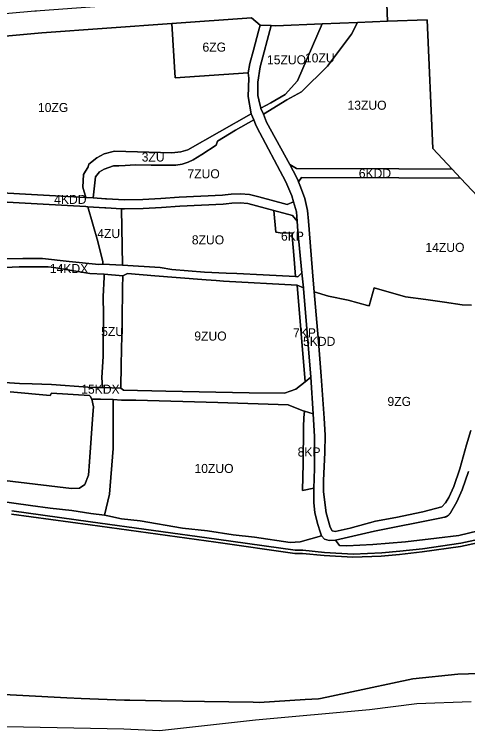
# Model space of a CAD drawing. Extents: x 7417411 to 7420955, y 5545251 to 5546537.
# Drawn here: x 7420138 to 7420638, y 5545251 to 5546041 of the extents above; entities that cross this region are included whole.
import ezdxf

# ---------------------------------------------------------------- set-up
doc = ezdxf.new("R2010")
doc.units = 0
doc.layers.add('linie_rozgraniczajace', color=7, linetype='Continuous')
doc.layers.add('oznaczenia_przeznaczen', color=7, linetype='Continuous')

msp = doc.modelspace()

# ---------------------------------------------------------------- linework, layer by layer
at = {"layer": 'linie_rozgraniczajace'}
for points in [[(7420549.68, 5546033.24), (7420547.73, 5546081.2), (7420586.45, 5546082.77), (7420609, 5546083.69), (7420626.25, 5546084.39), (7420650.88, 5546084.15), (7420723.84, 5546106.56), (7420725.48, 5546091.44), (7420726.07, 5546087.79), (7420729, 5546075.63), (7420734.51, 5546063.64), (7420745.13, 5546048.91), (7420772.59, 5546019.84), (7420827.71, 5545793.69), (7420693.29, 5545793.41), (7420630.15, 5545860.23), (7420620.66, 5545870.27), (7420599.42, 5545892.75), (7420593.29, 5546035.01)], [(7420311.58, 5546030.68), (7420399.32, 5546036.96), (7420409, 5546029), (7420407.22, 5546022.29), (7420401.63, 5546001.22), (7420397.75, 5545986.58), (7420395.97, 5545976.33), (7420315.35, 5545971.04)], [(7420409.62, 5545937.58), (7420420.78, 5545943.38), (7420436.67, 5545952.35), (7420450.38, 5545967.4), (7420477.28, 5546030.3), (7420516.55, 5546031.9), (7420509.68, 5546018.99), (7420483.49, 5545983.7), (7420454.77, 5545955.32), (7420438.37, 5545946.45), (7420412.54, 5545930.62), (7420409.83, 5545937.09)], [(7420412.54, 5545930.62), (7420438.37, 5545946.45), (7420454.77, 5545955.32), (7420483.49, 5545983.7), (7420509.68, 5546018.99), (7420516.55, 5546031.9), (7420549.68, 5546033.24), (7420593.29, 5546035.01), (7420599.42, 5545892.75), (7420620.66, 5545870.27), (7420561.9, 5545870.54), (7420449.2, 5545870.81), (7420441.8, 5545875.21), (7420416.17, 5545922.01)], [(7420406.63, 5545951.44), (7420406.37, 5545966.02), (7420408.99, 5545983.08), (7420421.08, 5546028.46), (7420426.19, 5546028.23), (7420477.28, 5546030.3), (7420450.38, 5545967.4), (7420436.67, 5545952.35), (7420420.78, 5545943.38), (7420409.62, 5545937.58), (7420407.64, 5545946.76)], [(7420213.5, 5545850.07), (7420214.18, 5545864.21), (7420219.24, 5545872.82), (7420219.99, 5545875.81), (7420228.89, 5545882.73), (7420236.89, 5545887.08), (7420248.36, 5545889.85), (7420311.71, 5545888.04), (7420321.7, 5545889.12), (7420329.43, 5545891.48), (7420399.25, 5545931.11), (7420402.01, 5545924.55), (7420381.77, 5545913.12), (7420361.98, 5545900.88), (7420360.67, 5545896.5), (7420344.81, 5545886.32), (7420335.17, 5545880.56), (7420329.45, 5545877.87), (7420322.83, 5545875.7), (7420316.1, 5545874.61), (7420305.12, 5545874.36), (7420288.91, 5545874.59), (7420271.15, 5545874.73), (7420260.03, 5545874.3), (7420253.08, 5545873.95), (7420247.32, 5545873.9), (7420236.88, 5545870.16), (7420231.96, 5545867), (7420227.53, 5545861.6), (7420224.72, 5545838.38), (7420217.44, 5545838.82), (7420216.76, 5545838.86)], [(7420224.72, 5545838.38), (7420227.53, 5545861.6), (7420231.96, 5545867), (7420236.88, 5545870.16), (7420247.32, 5545873.9), (7420253.08, 5545873.95), (7420260.03, 5545874.3), (7420271.15, 5545874.73), (7420288.91, 5545874.59), (7420305.12, 5545874.36), (7420316.1, 5545874.61), (7420322.83, 5545875.7), (7420329.45, 5545877.87), (7420335.17, 5545880.56), (7420344.81, 5545886.32), (7420360.67, 5545896.5), (7420361.98, 5545900.88), (7420381.77, 5545913.12), (7420402.01, 5545924.55), (7420404.07, 5545919.66), (7420405.46, 5545916.36), (7420437.42, 5545856.26), (7420443.87, 5545840.74), (7420445.93, 5545834.02), (7420438.75, 5545830.95), (7420407.56, 5545839.5), (7420397.22, 5545842.04), (7420387.44, 5545842.88), (7420377.1, 5545842.58), (7420370.37, 5545841.76), (7420367.42, 5545841.36), (7420319.7, 5545839.23), (7420299.6, 5545837.83), (7420279.54, 5545836.78), (7420259.46, 5545836.2), (7420239.44, 5545837.49), (7420238.46, 5545837.55)], [(7420441.8, 5545875.21), (7420449.2, 5545870.81), (7420561.9, 5545870.54), (7420620.66, 5545870.27), (7420630.15, 5545860.23), (7420561.86, 5545860.54), (7420454.72, 5545860.8), (7420451.47, 5545856.11), (7420450.64, 5545858.37), (7420445.6, 5545868.28)], [(7420218.85, 5545828.72), (7420237.85, 5545827.57), (7420238.81, 5545827.51), (7420256.11, 5545826.4), (7420257.17, 5545764.03), (7420235.59, 5545765.33), (7420235.53, 5545767.93), (7420230.09, 5545790.18)], [(7420257.17, 5545764.03), (7420256.11, 5545826.4), (7420259.29, 5545826.19), (7420279.94, 5545826.79), (7420300.21, 5545827.85), (7420320.27, 5545829.24), (7420368.32, 5545831.4), (7420371.64, 5545831.85), (7420377.84, 5545832.6), (7420387.16, 5545832.87), (7420395.59, 5545832.15), (7420405.04, 5545829.82), (7420424.16, 5545824.58), (7420426.5, 5545800.48), (7420433.56, 5545799.64), (7420444.66, 5545799.96), (7420444.4, 5545796.2), (7420445.68, 5545779.62), (7420446.83, 5545766.11), (7420447.9, 5545751.54), (7420412.28, 5545753.44), (7420383.22, 5545754.99), (7420371.38, 5545755.22), (7420347.53, 5545756.55), (7420311.55, 5545759.45), (7420298.58, 5545761.69)], [(7420424.16, 5545824.58), (7420444.7, 5545818.95), (7420449.84, 5545812.63), (7420450.54, 5545801.74), (7420455.02, 5545755.91), (7420450.52, 5545751.33), (7420447.9, 5545751.54), (7420446.83, 5545766.11), (7420445.68, 5545779.62), (7420444.4, 5545796.2), (7420444.66, 5545799.96), (7420433.56, 5545799.64), (7420426.5, 5545800.48)], [(7420255.48, 5545628.56), (7420255.88, 5545654.51), (7420256.63, 5545703.06), (7420257.19, 5545739.02), (7420257.39, 5545752.37), (7420262.63, 5545755.02), (7420293.01, 5545752.57), (7420344.56, 5545748.43), (7420349.39, 5545748.04), (7420360.64, 5545747.14), (7420368.45, 5545746.7), (7420449.8, 5545742.11), (7420458.59, 5545635.39), (7420448.38, 5545627.55), (7420435.87, 5545622.9), (7420396.79, 5545623.49), (7420304.83, 5545625.3), (7420258.1, 5545626.42)], [(7420234.38, 5545640.35), (7420235.68, 5545663.55), (7420236.21, 5545709.56), (7420235.94, 5545729.77), (7420237.04, 5545750.93), (7420236.91, 5545754.1), (7420257.39, 5545752.37), (7420257.19, 5545739.02), (7420256.63, 5545703.06), (7420255.88, 5545654.51), (7420255.48, 5545628.56), (7420235.08, 5545629.07)], [(7420449.8, 5545742.11), (7420449.98, 5545742.1), (7420456.88, 5545739.33), (7420456.95, 5545738.44), (7420464.84, 5545640.48), (7420458.59, 5545635.39)], [(7420237.5, 5545488.39), (7420242.85, 5545511.38), (7420246.89, 5545561.88), (7420246.81, 5545587.87), (7420246.82, 5545615.97), (7420255.97, 5545615.4), (7420271.94, 5545615.08), (7420362.25, 5545612.52), (7420439.92, 5545610.15), (7420457.39, 5545603.27), (7420457.89, 5545603.13), (7420457.23, 5545596.29), (7420456.97, 5545585.54), (7420456.42, 5545545.55), (7420455.82, 5545515.52), (7420468.36, 5545518.32), (7420468.21, 5545501.91), (7420469.34, 5545491.35), (7420472.14, 5545479.1), (7420475.44, 5545468.83), (7420476.53, 5545465.42), (7420453.04, 5545459.11), (7420442.29, 5545458.22), (7420402.85, 5545464.11), (7420379.1, 5545466.57), (7420351.1, 5545470.94), (7420323.49, 5545473.92), (7420276.77, 5545482.08), (7420256.26, 5545484.48), (7420240.91, 5545487.68)], [(7420455.82, 5545515.52), (7420456.42, 5545545.55), (7420456.97, 5545585.54), (7420457.23, 5545596.29), (7420457.89, 5545603.13), (7420467.47, 5545600.36), (7420468.95, 5545575), (7420468.86, 5545540.26), (7420468.44, 5545528.34), (7420468.36, 5545518.32)]]:
    msp.add_lwpolyline(points, close=True, dxfattribs=at)
for points in [[(7419980.1, 5546028.55), (7420160.42, 5546044.76), (7420162.3, 5546044.92), (7420166.39, 5546045.27), (7420221.35, 5546049.28), (7420309.21, 5546055.57), (7420395.44, 5546066.68), (7420396.55, 5546067.81), (7420416.28, 5546087.9), (7420428.12, 5546089.95), (7420441.86, 5546076.9), (7420491.12, 5546078.9), (7420528.94, 5546080.44), (7420547.73, 5546081.2), (7420549.68, 5546033.24), (7420516.55, 5546031.9), (7420477.28, 5546030.3), (7420426.19, 5546028.23), (7420421.08, 5546028.46), (7420409, 5546029), (7420399.32, 5546036.96), (7420311.58, 5546030.68), (7420168.36, 5546020.35), (7419957.04, 5546001.38)], [(7419957.04, 5546001.38), (7420168.36, 5546020.35), (7420311.58, 5546030.68), (7420315.35, 5545971.04), (7420395.97, 5545976.33), (7420396.41, 5545970.34), (7420395.65, 5545950.37), (7420399.25, 5545931.11), (7420329.43, 5545891.48), (7420321.7, 5545889.12), (7420311.71, 5545888.04), (7420248.36, 5545889.85), (7420236.89, 5545887.08), (7420228.89, 5545882.73), (7420219.99, 5545875.81), (7420219.24, 5545872.82), (7420214.18, 5545864.21), (7420213.5, 5545850.07), (7420216.76, 5545838.86), (7420170.21, 5545841.46), (7420110.4, 5545844.83)], [(7420395.65, 5545950.37), (7420396.41, 5545970.34), (7420395.97, 5545976.33), (7420397.75, 5545986.58), (7420401.63, 5546001.22), (7420407.22, 5546022.29), (7420409, 5546029), (7420421.08, 5546028.46), (7420408.99, 5545983.08), (7420406.37, 5545966.02), (7420406.63, 5545951.44), (7420407.64, 5545946.76), (7420409.62, 5545937.58), (7420409.83, 5545937.09), (7420412.54, 5545930.62), (7420416.17, 5545922.01), (7420441.8, 5545875.21), (7420445.6, 5545868.28), (7420450.64, 5545858.37), (7420451.47, 5545856.11), (7420453.48, 5545850.64), (7420458.49, 5545837.58), (7420461.15, 5545824.59), (7420462.31, 5545812.8), (7420467.64, 5545747.76), (7420468.73, 5545734.78), (7420471.55, 5545701.03), (7420473.29, 5545680.14), (7420476.33, 5545641.67), (7420479.54, 5545595.5), (7420480.57, 5545576.69), (7420480.24, 5545557.61), (7420479.02, 5545526.52), (7420478.8, 5545513.97), (7420481.85, 5545490.9), (7420486.13, 5545475.27), (7420488.44, 5545471.01), (7420491.78, 5545470.18), (7420508.48, 5545474.09), (7420536.38, 5545481.76), (7420558.69, 5545485.82), (7420588.4, 5545492.13), (7420609.56, 5545497.72), (7420613.49, 5545502.07), (7420617.27, 5545508), (7420622.61, 5545519.92), (7420629.3, 5545539.5), (7420636.81, 5545566.01), (7420641.46, 5545581.96)], [(7420618.66, 5545490.51), (7420618.55, 5545490.34), (7420618.43, 5545490.18), (7420618.32, 5545490.02), (7420618.19, 5545489.86), (7420618.07, 5545489.7), (7420617.95, 5545489.54), (7420617.82, 5545489.39), (7420617.68, 5545489.24), (7420617.55, 5545489.1), (7420617.41, 5545488.95), (7420617.27, 5545488.81), (7420617.12, 5545488.67), (7420616.98, 5545488.54), (7420616.83, 5545488.4), (7420616.68, 5545488.27), (7420616.52, 5545488.15), (7420616.36, 5545488.02), (7420616.2, 5545487.9), (7420616.04, 5545487.79), (7420615.88, 5545487.67), (7420615.71, 5545487.56), (7420615.54, 5545487.45), (7420615.37, 5545487.35), (7420615.2, 5545487.25), (7420615.02, 5545487.15), (7420614.85, 5545487.06), (7420614.67, 5545486.97), (7420614.49, 5545486.88), (7420614.31, 5545486.8), (7420614.12, 5545486.72), (7420613.94, 5545486.64), (7420613.75, 5545486.57), (7420613.56, 5545486.51), (7420613.37, 5545486.44), (7420613.18, 5545486.38), (7420612.99, 5545486.33), (7420612.8, 5545486.27), (7420612.6, 5545486.22), (7420612.41, 5545486.18), (7420612.21, 5545486.14), (7420607.16, 5545485.13), (7420535.33, 5545470.86), (7420492.19, 5545460.95), (7420485.2, 5545460.57), (7420479.85, 5545461.85), (7420476.53, 5545465.42), (7420475.44, 5545468.83), (7420472.14, 5545479.1), (7420469.34, 5545491.35), (7420468.21, 5545501.91), (7420468.36, 5545518.32), (7420468.44, 5545528.34), (7420468.86, 5545540.26), (7420468.95, 5545575), (7420467.47, 5545600.36), (7420464.84, 5545640.48), (7420456.95, 5545738.44), (7420456.88, 5545739.33), (7420455.02, 5545755.91), (7420450.54, 5545801.74), (7420449.84, 5545812.63), (7420449.17, 5545823.19), (7420445.93, 5545834.02), (7420443.87, 5545840.74), (7420437.42, 5545856.26), (7420405.46, 5545916.36), (7420404.07, 5545919.66), (7420402.01, 5545924.55), (7420399.25, 5545931.11), (7420395.65, 5545950.37)], [(7420642.1, 5545719.94), (7420632.02, 5545720.48), (7420612.21, 5545723.27), (7420591.7, 5545726.35), (7420569.18, 5545729.25), (7420534.61, 5545739.32), (7420529.17, 5545719.24), (7420527.46, 5545719.73), (7420505.97, 5545725.73), (7420484.56, 5545729.99), (7420468.73, 5545734.78), (7420467.64, 5545747.76), (7420462.31, 5545812.8), (7420461.15, 5545824.59), (7420458.49, 5545837.58), (7420453.48, 5545850.64), (7420451.47, 5545856.11), (7420454.72, 5545860.8), (7420561.86, 5545860.54), (7420630.15, 5545860.23), (7420693.29, 5545793.41)], [(7420110.4, 5545844.83), (7420170.21, 5545841.46), (7420216.76, 5545838.86), (7420217.44, 5545838.82), (7420224.72, 5545838.38), (7420238.46, 5545837.55), (7420239.44, 5545837.49), (7420259.46, 5545836.2), (7420279.54, 5545836.78), (7420299.6, 5545837.83), (7420319.7, 5545839.23), (7420367.42, 5545841.36), (7420370.37, 5545841.76), (7420377.1, 5545842.58), (7420387.44, 5545842.88), (7420397.22, 5545842.04), (7420407.56, 5545839.5), (7420438.75, 5545830.95), (7420445.93, 5545834.02), (7420449.17, 5545823.19), (7420449.84, 5545812.63), (7420444.7, 5545818.95), (7420424.16, 5545824.58), (7420405.04, 5545829.82), (7420395.59, 5545832.15), (7420387.16, 5545832.87), (7420377.84, 5545832.6), (7420371.64, 5545831.85), (7420368.32, 5545831.4), (7420320.27, 5545829.24), (7420300.21, 5545827.85), (7420279.94, 5545826.79), (7420259.29, 5545826.19), (7420256.11, 5545826.4), (7420238.81, 5545827.51), (7420237.85, 5545827.57), (7420218.85, 5545828.72), (7420216.88, 5545828.84), (7420169.65, 5545831.47), (7420109.85, 5545834.85)], [(7420109.85, 5545834.85), (7420169.65, 5545831.47), (7420216.88, 5545828.84), (7420218.85, 5545828.72), (7420230.09, 5545790.18), (7420235.53, 5545767.93), (7420235.59, 5545765.33), (7420230.99, 5545764.82), (7420198.34, 5545768.17), (7420168.96, 5545771.59), (7420166.1, 5545771.58), (7420147.34, 5545771.5), (7420112.06, 5545771.08)], [(7420112.06, 5545771.08), (7420147.34, 5545771.5), (7420166.1, 5545771.58), (7420168.96, 5545771.59), (7420198.34, 5545768.17), (7420230.99, 5545764.82), (7420235.59, 5545765.33), (7420257.17, 5545764.03), (7420298.58, 5545761.69), (7420311.55, 5545759.45), (7420347.53, 5545756.55), (7420371.38, 5545755.22), (7420383.22, 5545754.99), (7420412.28, 5545753.44), (7420447.9, 5545751.54), (7420450.52, 5545751.33), (7420455.02, 5545755.91), (7420456.88, 5545739.33), (7420449.98, 5545742.1), (7420449.8, 5545742.11), (7420368.45, 5545746.7), (7420360.64, 5545747.14), (7420349.39, 5545748.04), (7420344.56, 5545748.43), (7420293.01, 5545752.57), (7420262.63, 5545755.02), (7420257.39, 5545752.37), (7420236.91, 5545754.1), (7420221.26, 5545755.14), (7420181.4, 5545761.61), (7420175.24, 5545762.34), (7420165.98, 5545762.33), (7420143.31, 5545762.32), (7420119.12, 5545761.17)], [(7420119.12, 5545761.17), (7420143.31, 5545762.32), (7420165.98, 5545762.33), (7420175.24, 5545762.34), (7420181.4, 5545761.61), (7420221.26, 5545755.14), (7420236.91, 5545754.1), (7420237.04, 5545750.93), (7420235.94, 5545729.77), (7420236.21, 5545709.56), (7420235.68, 5545663.55), (7420234.38, 5545640.35), (7420235.08, 5545629.07), (7420227.59, 5545629.35), (7420218.98, 5545629.67), (7420178.86, 5545632.49), (7420157.55, 5545633.28), (7420143.47, 5545633.81), (7420121.13, 5545635.19)], [(7420641.46, 5545581.96), (7420636.81, 5545566.01), (7420629.3, 5545539.5), (7420622.61, 5545519.92), (7420617.27, 5545508), (7420613.49, 5545502.07), (7420609.56, 5545497.72), (7420588.4, 5545492.13), (7420558.69, 5545485.82), (7420536.38, 5545481.76), (7420508.48, 5545474.09), (7420491.78, 5545470.18), (7420488.44, 5545471.01), (7420486.13, 5545475.27), (7420481.85, 5545490.9), (7420478.8, 5545513.97), (7420479.02, 5545526.52), (7420480.24, 5545557.61), (7420480.57, 5545576.69), (7420479.54, 5545595.5), (7420476.33, 5545641.67), (7420473.29, 5545680.14), (7420471.55, 5545701.03), (7420468.73, 5545734.78), (7420484.56, 5545729.99), (7420505.97, 5545725.73), (7420527.46, 5545719.73), (7420529.17, 5545719.24), (7420534.61, 5545739.32), (7420569.18, 5545729.25), (7420591.7, 5545726.35), (7420612.21, 5545723.27), (7420632.02, 5545720.48), (7420642.1, 5545719.94)], [(7420121.13, 5545635.19), (7420143.47, 5545633.81), (7420157.55, 5545633.28), (7420178.86, 5545632.49), (7420218.98, 5545629.67), (7420227.59, 5545629.35), (7420235.08, 5545629.07), (7420255.48, 5545628.56), (7420258.1, 5545626.42), (7420304.83, 5545625.3), (7420396.79, 5545623.49), (7420435.87, 5545622.9), (7420448.38, 5545627.55), (7420458.59, 5545635.39), (7420464.84, 5545640.48), (7420467.47, 5545600.36), (7420457.89, 5545603.13), (7420457.39, 5545603.27), (7420439.92, 5545610.15), (7420362.25, 5545612.52), (7420271.94, 5545615.08), (7420255.97, 5545615.4), (7420246.82, 5545615.97), (7420233.05, 5545616.41), (7420233.03, 5545616.41), (7420223.5, 5545616.3), (7420221.63, 5545619.68), (7420220.66, 5545620.27), (7420178.73, 5545623.14), (7420177.52, 5545620.45), (7420133.26, 5545624.46)], [(7420133.26, 5545624.46), (7420177.52, 5545620.45), (7420178.73, 5545623.14), (7420220.66, 5545620.27), (7420221.63, 5545619.68), (7420223.5, 5545616.3), (7420225.24, 5545608.07), (7420224.63, 5545599.47), (7420220.88, 5545547.25), (7420219.59, 5545532.66), (7420215.65, 5545522.15), (7420209.67, 5545518.07), (7420200.88, 5545517.97), (7420111.11, 5545528.55)], [(7420111.11, 5545528.55), (7420200.88, 5545517.97), (7420209.67, 5545518.07), (7420215.65, 5545522.15), (7420219.59, 5545532.66), (7420220.88, 5545547.25), (7420224.63, 5545599.47), (7420225.24, 5545608.07), (7420223.5, 5545616.3), (7420233.03, 5545616.41), (7420233.05, 5545616.41), (7420246.82, 5545615.97), (7420246.81, 5545587.87), (7420246.89, 5545561.88), (7420242.85, 5545511.38), (7420237.5, 5545488.39), (7420222.4, 5545490.26), (7420201.32, 5545493.36), (7420177.35, 5545496), (7420155.78, 5545499.11), (7420115.86, 5545504.53)], [(7420649.57, 5545471.08), (7420628.37, 5545465.97), (7420603.54, 5545463.1), (7420569.34, 5545459.04), (7420533.41, 5545456.15), (7420504.79, 5545454.67), (7420496.41, 5545454.75), (7420492.19, 5545460.95), (7420535.33, 5545470.86), (7420607.16, 5545485.13), (7420612.21, 5545486.14), (7420612.41, 5545486.18), (7420612.6, 5545486.22), (7420612.8, 5545486.27), (7420612.99, 5545486.33), (7420613.18, 5545486.38), (7420613.37, 5545486.44), (7420613.56, 5545486.51), (7420613.75, 5545486.57), (7420613.94, 5545486.64), (7420614.12, 5545486.72), (7420614.31, 5545486.8), (7420614.49, 5545486.88), (7420614.67, 5545486.97), (7420614.85, 5545487.06), (7420615.02, 5545487.15), (7420615.2, 5545487.25), (7420615.37, 5545487.35), (7420615.54, 5545487.45), (7420615.71, 5545487.56), (7420615.88, 5545487.67), (7420616.04, 5545487.79), (7420616.2, 5545487.9), (7420616.36, 5545488.02), (7420616.52, 5545488.15), (7420616.68, 5545488.27), (7420616.83, 5545488.4), (7420616.98, 5545488.54), (7420617.12, 5545488.67), (7420617.27, 5545488.81), (7420617.41, 5545488.95), (7420617.55, 5545489.1), (7420617.68, 5545489.24), (7420617.82, 5545489.39), (7420617.95, 5545489.54), (7420618.07, 5545489.7), (7420618.19, 5545489.86), (7420618.32, 5545490.02), (7420618.43, 5545490.18), (7420618.55, 5545490.34), (7420618.66, 5545490.51), (7420618.76, 5545490.68), (7420618.87, 5545490.85), (7420618.9, 5545490.91), (7420626.09, 5545503.25), (7420631.92, 5545516.25), (7420638.85, 5545536.52)], [(7420638.85, 5545536.52), (7420631.92, 5545516.25), (7420626.09, 5545503.25), (7420618.9, 5545490.91), (7420618.87, 5545490.85), (7420618.76, 5545490.68), (7420618.66, 5545490.51)], [(7420115.86, 5545504.53), (7420155.78, 5545499.11), (7420177.35, 5545496), (7420201.32, 5545493.36), (7420222.4, 5545490.26), (7420237.5, 5545488.39), (7420240.91, 5545487.68), (7420256.26, 5545484.48), (7420276.77, 5545482.08), (7420323.49, 5545473.92)], [(7420134.57, 5545489.53), (7420221.39, 5545477.63), (7420360.27, 5545458.59), (7420447.1, 5545446.17), (7420455.75, 5545446.27), (7420479.58, 5545443.72), (7420511.08, 5545442.05), (7420542.6, 5545443.33), (7420562.68, 5545445.07), (7420587.64, 5545447.88), (7420629.98, 5545453.99), (7420662.47, 5545460.85)], [(7420479.58, 5545443.72), (7420455.75, 5545446.27), (7420447.1, 5545446.17), (7420360.27, 5545458.59), (7420221.39, 5545477.63), (7420134.57, 5545489.53)], [(7420662.97, 5545464.32), (7420630.48, 5545457.45), (7420588.14, 5545451.34), (7420563.17, 5545448.54), (7420543.1, 5545446.8), (7420511.58, 5545445.52), (7420480.07, 5545447.19), (7420456.25, 5545449.73), (7420447.6, 5545449.63), (7420360.76, 5545462.06), (7420221.87, 5545481.1), (7420135.05, 5545493)], [(7420135.05, 5545493), (7420221.87, 5545481.1), (7420360.76, 5545462.06), (7420447.6, 5545449.63), (7420456.25, 5545449.73), (7420480.07, 5545447.19), (7420511.58, 5545445.52), (7420543.1, 5545446.8), (7420563.17, 5545448.54), (7420588.14, 5545451.34), (7420630.48, 5545457.45), (7420662.97, 5545464.32)], [(7420323.49, 5545473.92), (7420351.1, 5545470.94), (7420379.1, 5545466.57), (7420402.85, 5545464.11), (7420442.29, 5545458.22), (7420453.04, 5545459.11), (7420476.53, 5545465.42), (7420479.85, 5545461.85), (7420485.2, 5545460.57), (7420492.19, 5545460.95), (7420496.41, 5545454.75), (7420504.79, 5545454.67), (7420533.41, 5545456.15), (7420569.34, 5545459.04), (7420603.54, 5545463.1), (7420628.37, 5545465.97), (7420649.57, 5545471.08)], [(7420662.47, 5545460.85), (7420629.98, 5545453.99), (7420587.64, 5545447.88), (7420562.68, 5545445.07), (7420542.6, 5545443.33), (7420511.08, 5545442.05), (7420479.58, 5545443.72)], [(7420800.27, 5545321.84), (7420781.98, 5545317.2), (7420697.16, 5545315.28), (7420627.06, 5545312.87), (7420577.45, 5545307.73), (7420505.14, 5545292.42), (7420475.69, 5545286.18), (7420473.37, 5545285.69), (7420458.6, 5545284.88), (7420407.79, 5545281.77), (7420401.44, 5545282.13), (7420347.71, 5545282.73), (7420299.98, 5545283.39), (7420265.23, 5545284.2), (7420259.55, 5545284.34), (7420211.59, 5545286.14), (7420195.89, 5545286.82), (7420105.46, 5545291.6)], [(7420105.46, 5545291.6), (7420195.89, 5545286.82), (7420211.59, 5545286.14), (7420259.55, 5545284.34), (7420265.23, 5545284.2), (7420299.98, 5545283.39), (7420347.71, 5545282.73), (7420401.44, 5545282.13), (7420407.79, 5545281.77), (7420458.6, 5545284.88), (7420473.37, 5545285.69), (7420475.69, 5545286.18), (7420505.14, 5545292.42), (7420577.45, 5545307.73), (7420627.06, 5545312.87), (7420697.16, 5545315.28)], [(7420641.64, 5545282.57), (7420581.74, 5545280.24), (7420529.47, 5545273.62), (7420403.99, 5545262.07), (7420298.11, 5545250.62), (7420258.68, 5545252.15), (7420092.31, 5545255.64)]]:
    msp.add_lwpolyline(points, dxfattribs=at)

# ---------------------------------------------------------------- texts
at = {"layer": 'oznaczenia_przeznaczen'}
for s, p in [('6ZG', (7420345.4, 5545999.77)), ('15ZUO', (7420416.56, 5545985.78)), ('10ZU', (7420458.43, 5545987.84)), ('13ZUO', (7420505.36, 5545935.66)), ('10ZG', (7420163.92, 5545933.15)), ('3ZU', (7420278.35, 5545878.53)), ('7ZUO', (7420328.81, 5545860.01)), ('6KDD', (7420517.82, 5545860.55)), ('4KDD', (7420181.81, 5545831.79)), ('4ZU', (7420229.35, 5545794.09)), ('8ZUO', (7420333.66, 5545787.12)), ('6KP', (7420432.01, 5545791.2)), ('14ZUO', (7420591.31, 5545778.83)), ('14KDX', (7420177.07, 5545755.52)), ('5ZU', (7420233.63, 5545685.99)), ('7KP', (7420445.29, 5545684.58)), ('9ZUO', (7420336.39, 5545680.98)), ('5KDD', (7420456.32, 5545675.14)), ('15KDX', (7420211.64, 5545622.36)), ('9ZG', (7420549.45, 5545608.85)), ('8KP', (7420450.36, 5545553.11)), ('10ZUO', (7420336.59, 5545534.9))]:
    msp.add_text(s, height=10, dxfattribs=at).set_placement(p)

doc.saveas('drawing.dxf')
